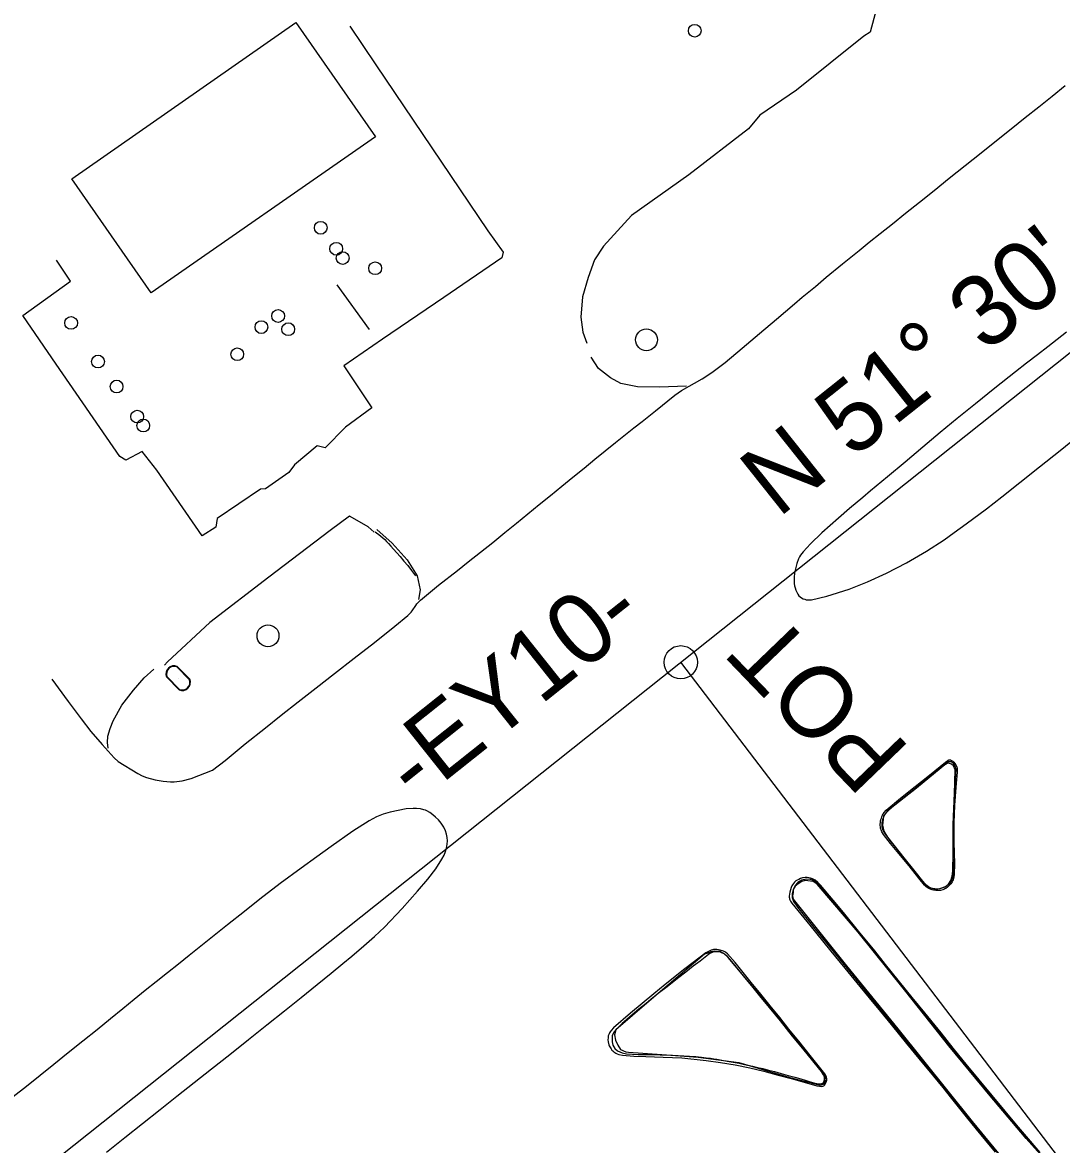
# Model space of a CAD drawing. Extents: x 471894 to 476235, y 503501 to 507878.
# Drawn here: x 473515.9 to 473749.9, y 506128.6 to 506381.3 of the extents above; entities that cross this region are included whole.
import ezdxf

# ---------------------------------------------------------------- set-up
doc = ezdxf.new("R2010")
doc.units = 0
for name, color, linetype in [('Exist Building Metal Canopy', 7, 'Continuous'), ('Exist Horizontal Alignment', 7, 'Continuous'), ('Exist Horizontal Alignment Direction Label', 7, 'Continuous'), ('Exist Other Culture Gas Pump or Vent CELL', 7, 'Continuous'), ('Exist Other Culture Sign', 7, 'Continuous'), ('Exist Roads Change in Surface', 7, 'Continuous'), ('Exist Roads Curbs', 7, 'Continuous'), ('Exist Roads EOP', 7, 'Continuous'), ('Exist Roads EOP Other', 7, 'Continuous'), ('Exist Utilities Other Pole CELL', 7, 'Continuous'), ('Exist Utilities Water Meter CELL', 7, 'Continuous')]:
    doc.layers.add(name, color=color, linetype=linetype)

msp = doc.modelspace()

# ---------------------------------------------------------------- linework, layer by layer
at = {"layer": 'Exist Building Metal Canopy'}
msp.add_lwpolyline([(473526.96, 506346.11), (473577.44, 506381.28), (473595.35, 506355.57), (473544.87, 506320.4)], close=True, dxfattribs=at)
at = {"layer": 'Exist Horizontal Alignment'}
for p, q in [((473294.53, 505943.19), (474190.95, 506656.19)), ((473908.93, 505916.58), (473664.15, 506237.18))]:
    msp.add_line(p, q, dxfattribs=at)
msp.add_circle((473664.15, 506237.18), 3.75, dxfattribs=at)
at = {"layer": 'Exist Other Culture Gas Pump or Vent CELL'}
for centre in [(473667.3, 506379.44), (473583.05, 506335.06), (473586.53, 506330.33), (473587.99, 506328.23), (473595.31, 506325.95), (473526.82, 506313.63), (473573.45, 506315.19), (473569.68, 506312.68), (473575.72, 506312.21), (473564.24, 506306.57), (473532.88, 506304.93), (473537.06, 506299.3), (473541.7, 506292.53), (473543.06, 506290.52)]:
    msp.add_circle(centre, 1.44, dxfattribs=at)
at = {"layer": 'Exist Other Culture Sign'}
msp.add_line((473586.7, 506322.18), (473593.99, 506312.17), dxfattribs=at)
at = {"layer": 'Exist Roads Change in Surface'}
msp.add_lwpolyline([(473589.57, 506380.48), (473595.45, 506371.78), (473608.09, 506353.04), (473620.65, 506334.35), (473624.15, 506329.58), (473623.82, 506328.26), (473610.77, 506319.39), (473596.97, 506309.97), (473588.23, 506303.98), (473594.52, 506294.5), (473588.62, 506290.12), (473584.06, 506285.52), (473582.27, 506285.91), (473577.14, 506281.7), (473575.88, 506279.92), (473570.61, 506276.26), (473569.47, 506276.21), (473559.71, 506269.56), (473559.45, 506267.65), (473556.36, 506265.64), (473546.1, 506280.44), (473542.79, 506284.65), (473539.11, 506282.73), (473537.76, 506283.53), (473523.42, 506304.36), (473515.97, 506315.3), (473526.7, 506323.07), (473523.49, 506327.77)], dxfattribs=at)
at = {"layer": 'Exist Roads Curbs'}
for points in [[(473709.21, 506388.16), (473706.82, 506379.16), (473705.37, 506378.24), (473690.19, 506366.08), (473681.93, 506360.43), (473679.38, 506357.38), (473666, 506346.95), (473653.06, 506337.8), (473646.77, 506330.9), (473644.73, 506327.81), (473643.25, 506323.85), (473641.98, 506319.48), (473641.64, 506314.93), (473642.08, 506311.54), (473642.95, 506309.04)], [(473595.11, 506266.53), (473593.76, 506267.7), (473590.76, 506269.45), (473589.49, 506270.1), (473585.2, 506266.84), (473571.36, 506256.37), (473558.07, 506246.18), (473548.51, 506237.26), (473547.88, 506236.53)], [(473595.33, 506266.57), (473595.6, 506266.37), (473596.15, 506265.96), (473596.6, 506265.6), (473597.02, 506265.25), (473597.45, 506264.85), (473597.89, 506264.4), (473598.34, 506263.91), (473598.85, 506263.34), (473599.45, 506262.66), (473600.15, 506261.87), (473600.95, 506260.98), (473601.79, 506260), (473602.64, 506258.95), (473603.5, 506257.83), (473604.36, 506256.63)], [(473710.62, 506203.68), (473709.85, 506202.51), (473709.56, 506200.49), (473709.89, 506199.15), (473710.71, 506197.76), (473716.92, 506189.92), (473719.65, 506186.64), (473721.43, 506186.1), (473722.5, 506186.22), (473723.75, 506186.7), (473724.46, 506187.24), (473724.96, 506188.04), (473725.3, 506189.01), (473725.4, 506190.21), (473725.62, 506202.05), (473725.96, 506212.96), (473725.61, 506213.84), (473725.12, 506214.23), (473724.7, 506214.42), (473724.28, 506214.46), (473723.65, 506214.11), (473717.26, 506208.85), (473710.62, 506203.68)], [(473745.45, 506126.08), (473742.7, 506129.22), (473739.64, 506132.86), (473735.5, 506137.86), (473728.01, 506147.03), (473721.99, 506154.36), (473716.94, 506160.6), (473712.88, 506165.51), (473706.36, 506173.66), (473702.31, 506178.71), (473700.06, 506181.42), (473698.53, 506183.22), (473695.47, 506186.85), (473694.74, 506187.54), (473694.01, 506188.05), (473693.37, 506188.29), (473692.4, 506188.32), (473691.42, 506188.09), (473690.52, 506187.55), (473689.9, 506186.92), (473689.47, 506185.98), (473689.24, 506185.1), (473689.21, 506184.19), (473689.55, 506183.27), (473690.77, 506181.67), (473694.14, 506177.44), (473702.87, 506166.63), (473712.72, 506154.53), (473723.14, 506141.86), (473731.9, 506131.08), (473742.1, 506118.69)], [(473748.94, 506122.09), (473741.98, 506129.92), (473733.82, 506139.54), (473724.5, 506150.77), (473714.56, 506163.42), (473704.13, 506176.36), (473694.87, 506187.18), (473693.94, 506187.8), (473692.18, 506188), (473691.45, 506187.8), (473690.59, 506187.26), (473689.92, 506186.75), (473689.5, 506185.99), (473689.43, 506185.3), (473689.34, 506184.55), (473689.45, 506183.82)], [(473689.45, 506183.82), (473701.49, 506168.84), (473713.06, 506154.62), (473729.8, 506133.75), (473747.2, 506112.55)], [(473653.27, 506148.91), (473654.58, 506148.87), (473656.2, 506148.84), (473657.91, 506148.81), (473659.5, 506148.78), (473660.95, 506148.74), (473662.26, 506148.69), (473663.53, 506148.64), (473664.83, 506148.56), (473666.15, 506148.47), (473667.51, 506148.36), (473668.79, 506148.24), (473669.89, 506148.12), (473670.83, 506148), (473671.59, 506147.88), (473672.28, 506147.75), (473673.02, 506147.63), (473673.8, 506147.5), (473674.62, 506147.36), (473675.48, 506147.22), (473676.37, 506147.05), (473677.28, 506146.87), (473678.22, 506146.67), (473679.21, 506146.45), (473680.27, 506146.21), (473681.41, 506145.94), (473682.61, 506145.65), (473683.9, 506145.33), (473685.29, 506144.98), (473686.77, 506144.58), (473688.34, 506144.14), (473689.86, 506143.71), (473691.2, 506143.33), (473692.36, 506142.99), (473693.33, 506142.69), (473694.14, 506142.46), (473694.79, 506142.3), (473695.29, 506142.22), (473695.64, 506142.22), (473695.9, 506142.28), (473696.11, 506142.38), (473696.28, 506142.54), (473696.4, 506142.75), (473696.49, 506142.98), (473696.53, 506143.22), (473696.54, 506143.46), (473696.52, 506143.71), (473696.44, 506143.97), (473696.3, 506144.28), (473696.09, 506144.62), (473695.82, 506145), (473695.18, 506145.8), (473693.89, 506147.39), (473691.95, 506149.79), (473689.35, 506152.99), (473686.58, 506156.39), (473684.12, 506159.41), (473681.97, 506162.05), (473680.13, 506164.3), (473678.58, 506166.19), (473677.32, 506167.74), (473676.34, 506168.93), (473675.64, 506169.79), (473675.12, 506170.4), (473674.68, 506170.88), (473674.32, 506171.22), (473674.04, 506171.43), (473673.8, 506171.56), (473673.56, 506171.67), (473673.32, 506171.77), (473673.08, 506171.86), (473672.83, 506171.93), (473672.56, 506171.97), (473672.27, 506171.98), (473671.96, 506171.97), (473671.64, 506171.94), (473671.35, 506171.87), (473671.09, 506171.77), (473670.84, 506171.64), (473670.43, 506171.35), (473669.64, 506170.76), (473668.48, 506169.88), (473666.96, 506168.7), (473665.29, 506167.41), (473663.7, 506166.18), (473662.19, 506165.01), (473660.76, 506163.89), (473659.34, 506162.78), (473657.87, 506161.6), (473656.33, 506160.35), (473654.73, 506159.04), (473653.22, 506157.79), (473651.96, 506156.71), (473650.93, 506155.81), (473650.16, 506155.08), (473649.57, 506154.47), (473649.14, 506153.93), (473648.86, 506153.44), (473648.72, 506153.01), (473648.69, 506152.6), (473648.68, 506152.17), (473648.72, 506151.71), (473648.84, 506150.92), (473649.31, 506150.16), (473649.93, 506149.66), (473650.96, 506149.24), (473651.92, 506148.99), (473653.27, 506148.91)], [(473669.51, 506171.43), (473657.59, 506161.29), (473649.5, 506154.43), (473649.23, 506153.27), (473649.41, 506152.09), (473649.94, 506150.92), (473650.58, 506149.97), (473651.77, 506149.42), (473652.37, 506149.34), (473659.9, 506148.84), (473668.08, 506148.24), (473677.22, 506147), (473688.46, 506143.72), (473695.24, 506142.02), (473695.69, 506141.94), (473696.34, 506142.25), (473696.68, 506142.76), (473696.88, 506143.23), (473696.67, 506143.65), (473696.42, 506144.29), (473686.28, 506157.01), (473674.82, 506170.65), (473673.84, 506171.59), (473673.03, 506172.02), (473671.82, 506172.12), (473670.94, 506171.93), (473670.24, 506171.69), (473669.51, 506171.43)]]:
    msp.add_lwpolyline(points, dxfattribs=at)
msp.add_lwpolyline([(473719.28, 506187.15), (473716.68, 506190.4), (473714.47, 506193.13), (473711.34, 506197.02), (473709.95, 506198.93), (473709.7, 506199.41), (473709.59, 506199.76), (473709.53, 506200.08), (473709.49, 506200.4), (473709.48, 506200.73), (473709.51, 506201.06), (473709.56, 506201.4), (473709.65, 506201.74), (473709.76, 506202.08), (473709.9, 506202.41), (473710.07, 506202.72), (473710.48, 506203.33), (473710.99, 506203.9), (473712.96, 506205.61), (473716.83, 506208.68), (473721.2, 506212.19), (473724.09, 506214.54), (473724.35, 506214.74), (473724.5, 506214.82), (473724.59, 506214.85), (473724.67, 506214.87), (473724.76, 506214.87), (473724.85, 506214.87), (473724.94, 506214.85), (473725.04, 506214.82), (473725.14, 506214.78), (473725.24, 506214.72), (473725.34, 506214.64), (473725.43, 506214.55), (473725.6, 506214.33), (473725.75, 506214.1), (473725.88, 506213.86), (473725.98, 506213.61), (473726.06, 506213.36), (473726.08, 506213.23), (473726.09, 506213.09), (473725.94, 506210.69), (473725.75, 506207.74), (473725.57, 506204.18), (473725.44, 506200.62), (473725.42, 506195.11), (473725.49, 506190.81), (473725.45, 506189.04), (473725.4, 506188.74), (473725.34, 506188.51), (473725.25, 506188.28), (473725.14, 506188.06), (473725.01, 506187.84), (473724.86, 506187.62), (473724.51, 506187.22), (473724.14, 506186.89), (473723.79, 506186.63), (473723.61, 506186.53), (473723.41, 506186.44), (473722.98, 506186.29), (473722.51, 506186.18), (473722.05, 506186.11), (473721.82, 506186.1), (473721.58, 506186.1), (473721.34, 506186.13), (473720.82, 506186.23), (473720.55, 506186.31), (473720.26, 506186.42), (473719.96, 506186.58), (473719.64, 506186.81)], close=True, dxfattribs=at)
at = {"layer": 'Exist Roads EOP'}
for points in [[(473522.46, 506233.36), (473526.12, 506228.38), (473529.06, 506224.46), (473531.28, 506221.61), (473533.83, 506218.64), (473536.53, 506215.66), (473537.45, 506214.82), (473541.81, 506212.12), (473542.81, 506211.64), (473543.81, 506211.25), (473545.75, 506210.72), (473547.53, 506210.4), (473549.19, 506210.25), (473550.05, 506210.27), (473551.85, 506210.5), (473553.86, 506211), (473558.7, 506212.85), (473561.54, 506215.06), (473566.05, 506218.78), (473570.58, 506222.44), (473574.1, 506225.24), (473577.98, 506228.27), (473582, 506231.42), (473586.15, 506234.66), (473590.59, 506238.13), (473595.15, 506241.68), (473599.77, 506245.29), (473602.7, 506247.76), (473603.41, 506248.49), (473603.65, 506248.77), (473604.43, 506250), (473604.71, 506250.35), (473605.51, 506251.18), (473609.61, 506254.52), (473613.83, 506257.86), (473616.29, 506259.82), (473619, 506261.98), (473621.79, 506264.2), (473624.51, 506266.39), (473627.16, 506268.53), (473629.73, 506270.63), (473632.26, 506272.71), (473634.79, 506274.78), (473637.33, 506276.85), (473639.86, 506278.91), (473642.37, 506280.94), (473644.8, 506282.91), (473649.46, 506286.66), (473653.61, 506289.98), (473655.42, 506291.42), (473658.45, 506293.83), (473662.84, 506297.32), (473664.32, 506298.37), (473668.99, 506301.07), (473671.17, 506302.47), (473674.16, 506304.74), (473678, 506307.91), (473681.88, 506311.21), (473685.74, 506314.51), (473689.77, 506317.94), (473691.51, 506319.41), (473694.47, 506321.87), (473696.93, 506323.93), (473700.56, 506326.95), (473704.31, 506329.97), (473706.58, 506331.8), (473709.08, 506333.79), (473711.81, 506335.97), (473714.76, 506338.32), (473717.9, 506340.82), (473721.19, 506343.45), (473724.63, 506346.2), (473728.22, 506349.08), (473731.82, 506351.96), (473735.27, 506354.72), (473738.57, 506357.36), (473741.73, 506359.87), (473744.79, 506362.31), (473747.79, 506364.72), (473750.73, 506367.09)], [(473751.06, 506311.56), (473746.8, 506308.23), (473744.48, 506306.43), (473742.04, 506304.53), (473739.58, 506302.61), (473734.89, 506298.91), (473730.51, 506295.4), (473726.43, 506292.09), (473722.6, 506288.92), (473718.69, 506285.64), (473714.68, 506282.26), (473710.71, 506278.94), (473706.87, 506275.77), (473705.15, 506274.34), (473702.16, 506271.81), (473699.7, 506269.68), (473695.93, 506266.32), (473693.37, 506263.87), (473691.68, 506262.06), (473691.12, 506261.32), (473690.89, 506260.94), (473690.68, 506260.49), (473690.29, 506259.41), (473689.98, 506258.27), (473689.79, 506257.29), (473689.69, 506256.36), (473689.68, 506255.4), (473689.72, 506254.91), (473689.8, 506254.42), (473689.92, 506253.92), (473690.07, 506253.42), (473690.27, 506252.95), (473690.5, 506252.54), (473690.76, 506252.19), (473691.05, 506251.9), (473691.36, 506251.67), (473691.7, 506251.49), (473692.06, 506251.37), (473692.43, 506251.29), (473692.82, 506251.25), (473693.22, 506251.25), (473693.63, 506251.27), (473697.03, 506252.06), (473702.08, 506253.69), (473706.21, 506255.31), (473710.52, 506257.26), (473714.99, 506259.61), (473719.47, 506262.22), (473723.46, 506264.79), (473725.76, 506266.39), (473728.46, 506268.36), (473733.01, 506271.76), (473736.49, 506274.45), (473740.51, 506277.65), (473744.93, 506281.19), (473749.58, 506284.89), (473752.01, 506286.81)], [(473725.91, 506214.4), (473726.12, 506214.06), (473726.26, 506213.79), (473726.34, 506213.57), (473726.38, 506213.38), (473726.4, 506213.22), (473726.38, 506212.47), (473726.19, 506209.95), (473725.83, 506205.03), (473725.66, 506201.01), (473725.66, 506196.62), (473725.77, 506191.89), (473725.72, 506189.42), (473725.63, 506188.75), (473725.56, 506188.47), (473725.48, 506188.2), (473725.37, 506187.95), (473725.25, 506187.7), (473725.11, 506187.47), (473724.96, 506187.26), (473724.62, 506186.87), (473724.24, 506186.53), (473723.83, 506186.24), (473723.61, 506186.12), (473723.39, 506186.02), (473723.16, 506185.93), (473722.66, 506185.81), (473722.13, 506185.75), (473721.58, 506185.76), (473721.04, 506185.84), (473720.78, 506185.9), (473720.53, 506185.99), (473720.05, 506186.21), (473719.64, 506186.47), (473719.46, 506186.61), (473719.07, 506186.99), (473717.75, 506188.58), (473715.57, 506191.31), (473713.64, 506193.66), (473711.39, 506196.4), (473709.85, 506198.41), (473709.47, 506199.01), (473709.27, 506199.43), (473709.17, 506199.77), (473709.11, 506200.09), (473709.08, 506200.41), (473709.08, 506200.74), (473709.1, 506201.07), (473709.15, 506201.4), (473709.23, 506201.74), (473709.33, 506202.08), (473709.46, 506202.41), (473709.62, 506202.73), (473709.99, 506203.33), (473710.45, 506203.89), (473713.63, 506206.58), (473716.96, 506209.22), (473720.17, 506211.77), (473723.81, 506214.71), (473724.27, 506215.06), (473724.36, 506215.12), (473724.45, 506215.15), (473724.53, 506215.18), (473724.62, 506215.19), (473724.71, 506215.2), (473724.8, 506215.19), (473724.9, 506215.18), (473725, 506215.15), (473725.12, 506215.1), (473725.27, 506215.02), (473725.44, 506214.9), (473725.66, 506214.7), (473725.91, 506214.4)], [(473534.78, 506126.86), (473538.9, 506130.14), (473542.92, 506133.33), (473546.84, 506136.44), (473550.66, 506139.46), (473554.5, 506142.5), (473558.46, 506145.63), (473562.54, 506148.86), (473566.76, 506152.18), (473570.94, 506155.49), (473574.91, 506158.66), (473578.67, 506161.69), (473582.23, 506164.58), (473585.4, 506167.18), (473588.02, 506169.32), (473590.08, 506171.02), (473592.79, 506173.31), (473595.15, 506175.4), (473597.41, 506177.54), (473601.4, 506181.73), (473604.83, 506185.6), (473607.19, 506188.33), (473608.97, 506190.66), (473610.36, 506192.85), (473610.84, 506193.76), (473611.16, 506194.55), (473611.39, 506195.35), (473611.54, 506196.19), (473611.59, 506196.97), (473611.54, 506197.7), (473611.39, 506198.45), (473611.15, 506199.23), (473610.74, 506200.07), (473610.17, 506200.96), (473609.56, 506201.71), (473608.93, 506202.32), (473608.28, 506202.86), (473607.63, 506203.32), (473606.96, 506203.69), (473606.62, 506203.85), (473606.27, 506203.97), (473605.49, 506204.16), (473604.64, 506204.25), (473603.84, 506204.28), (473602.27, 506204.16), (473598.67, 506203.39), (473597.14, 506202.94), (473595.63, 506202.36), (473593.96, 506201.5), (473590.29, 506199.13), (473585.4, 506195.67), (473582.18, 506193.37), (473578.65, 506190.84), (473573.94, 506187.36), (473569.31, 506183.79), (473565.84, 506181.05), (473562.04, 506178.03), (473557.92, 506174.75), (473553.39, 506171.13), (473550.97, 506169.2), (473548.49, 506167.22), (473546.01, 506165.23), (473543.53, 506163.23), (473541.05, 506161.22), (473538.46, 506159.12), (473535.66, 506156.85), (473532.65, 506154.42), (473529.44, 506151.83), (473526.15, 506149.18), (473522.95, 506146.61), (473519.82, 506144.1), (473516.77, 506141.66), (473513.8, 506139.29)], [(473745.07, 506126.78), (473741.54, 506130.87), (473739.76, 506132.99), (473737.21, 506136.06), (473734.27, 506139.6), (473731.36, 506143.13), (473728.46, 506146.68), (473725.53, 506150.27), (473722.77, 506153.69), (473719.1, 506158.2), (473716.3, 506161.65), (473713.1, 506165.59), (473710.24, 506169.14), (473707.84, 506172.16), (473704.2, 506176.65), (473701.1, 506180.42), (473699.27, 506182.63), (473695.62, 506186.99), (473694.99, 506187.6), (473694.4, 506188.07), (473694.1, 506188.25), (473693.81, 506188.41), (473693.56, 506188.52), (473693.34, 506188.59), (473693.02, 506188.65), (473692.61, 506188.68), (473692.18, 506188.68), (473691.75, 506188.64), (473691.54, 506188.6), (473691.11, 506188.46), (473690.71, 506188.29), (473690.38, 506188.12), (473690.09, 506187.92), (473689.8, 506187.66), (473689.53, 506187.35), (473689.3, 506187.02), (473689.19, 506186.84), (473689, 506186.42), (473688.84, 506185.93), (473688.72, 506185.43), (473688.64, 506184.94), (473688.6, 506184.49), (473688.6, 506184.28), (473688.62, 506184.08), (473688.65, 506183.89), (473688.7, 506183.71), (473688.76, 506183.54), (473688.85, 506183.36), (473689.14, 506182.92), (473692.52, 506178.79), (473694.48, 506176.4), (473697.97, 506172.13), (473701.1, 506168.29), (473704.47, 506164.17), (473707.64, 506160.3), (473709.1, 506158.53), (473711.52, 506155.56), (473714.96, 506151.35), (473716.72, 506149.21), (473718.84, 506146.63), (473721.07, 506143.93), (473723.16, 506141.37), (473725.12, 506138.95), (473728.77, 506134.43), (473730.7, 506132.04), (473732.76, 506129.5), (473734.94, 506126.82)]]:
    msp.add_lwpolyline(points, dxfattribs=at)
msp.add_lwpolyline([(473673.74, 506172.08), (473673.01, 506172.35), (473672.63, 506172.44), (473672.25, 506172.48), (473671.49, 506172.47), (473671.3, 506172.45), (473670.97, 506172.37), (473669.81, 506171.71), (473665.09, 506168.14), (473660.65, 506164.62), (473658.11, 506162.54), (473652.81, 506158.12), (473648.99, 506154.82), (473648.44, 506154.22), (473648.24, 506153.95), (473648.09, 506153.7), (473647.98, 506153.46), (473647.89, 506153.23), (473647.82, 506153.01), (473647.78, 506152.8), (473647.76, 506152.59), (473647.75, 506152.16), (473647.8, 506151.72), (473647.96, 506151.03), (473648.04, 506150.8), (473648.15, 506150.56), (473648.29, 506150.32), (473648.46, 506150.08), (473648.65, 506149.84), (473648.85, 506149.63), (473649.06, 506149.44), (473649.28, 506149.27), (473649.53, 506149.12), (473649.83, 506148.99), (473650.17, 506148.87), (473651, 506148.68), (473653.6, 506148.46), (473656.28, 506148.4), (473660.19, 506148.26), (473664.41, 506148.11), (473669.88, 506147.51), (473673.07, 506147.04), (473676.42, 506146.48), (473679.7, 506145.82), (473682.87, 506145.06), (473686.1, 506144.21), (473689.28, 506143.34), (473694.76, 506141.81), (473695.36, 506141.69), (473695.81, 506141.65), (473696.14, 506141.68), (473696.35, 506141.78), (473696.53, 506141.94), (473696.76, 506142.28), (473696.93, 506142.62), (473697, 506142.85), (473697.03, 506143.09), (473697.03, 506143.46), (473696.97, 506143.75), (473696.83, 506144.1), (473696.61, 506144.49), (473693.28, 506148.64), (473690.74, 506151.81), (473688.52, 506154.58), (473686.43, 506157.17), (473684.3, 506159.8), (473682.15, 506162.44), (473680.04, 506165.07), (473676.41, 506169.54), (473674.71, 506171.53), (473674.32, 506171.79), (473674.07, 506171.93)], close=True, dxfattribs=at)
at = {"layer": 'Exist Roads EOP Other'}
for points in [[(473665.47, 506299.42), (473659.38, 506299.14), (473654.39, 506299.21), (473650.63, 506300.01), (473648.31, 506301.29), (473645.65, 506303.38), (473643.93, 506305.93)], [(473595.7, 506267.08), (473599.13, 506264.04), (473602.48, 506260.26), (473604.8, 506256.69), (473605.43, 506253.49), (473605.1, 506251.34)], [(473535.13, 506217.85), (473535, 506219.14), (473535.12, 506220.54), (473535.63, 506222.3), (473536.3, 506223.99), (473538.24, 506227.55), (473540.89, 506230.89), (473543.29, 506233.66), (473545.47, 506235.61)]]:
    msp.add_lwpolyline(points, dxfattribs=at)
at = {"layer": 'Exist Utilities Other Pole CELL'}
for centre in [(473656.41, 506309.83), (473571.16, 506243.16)]:
    msp.add_circle(centre, 2.46, dxfattribs=at)
at = {"layer": 'Exist Utilities Water Meter CELL'}
msp.add_line((473550.94, 506233.61), (473550.94, 506233.61), dxfattribs=at)
for points in [[(473550.62, 506236.16), (473553.48, 506233.25)], [(473550.72, 506236.25), (473553.58, 506233.35)], [(473551.15, 506230.96), (473548.28, 506233.89)], [(473551.25, 506231.06), (473548.38, 506233.98)]]:
    msp.add_lwpolyline(points, dxfattribs=at)
for centre, radius, start, end in [((473550.02, 506234.54), 1.86, 67.7242, 200.5256), ((473550.02, 506234.53), 1.73, 69.8471, 198.3285), ((473551.84, 506232.69), 1.86, 248.1945, 20.8546), ((473551.85, 506232.68), 1.73, 249.6734, 19.419)]:
    msp.add_arc(centre, radius, start, end, dxfattribs=at)

# ---------------------------------------------------------------- texts
at = {"layer": 'Exist Horizontal Alignment'}
msp.add_text('POT', height=16, rotation=133.8986, dxfattribs=at).set_placement((473716.17, 506217.58))
at = {"layer": 'Exist Horizontal Alignment Direction Label'}
for s, p in [('N 51%%d 30\' 06" E', (473686.06, 506269.51)), ('-EY10-', (473604.59, 506205.19))]:
    msp.add_text(s, height=16, rotation=38.4983, dxfattribs=at).set_placement(p)

doc.saveas('drawing.dxf')
